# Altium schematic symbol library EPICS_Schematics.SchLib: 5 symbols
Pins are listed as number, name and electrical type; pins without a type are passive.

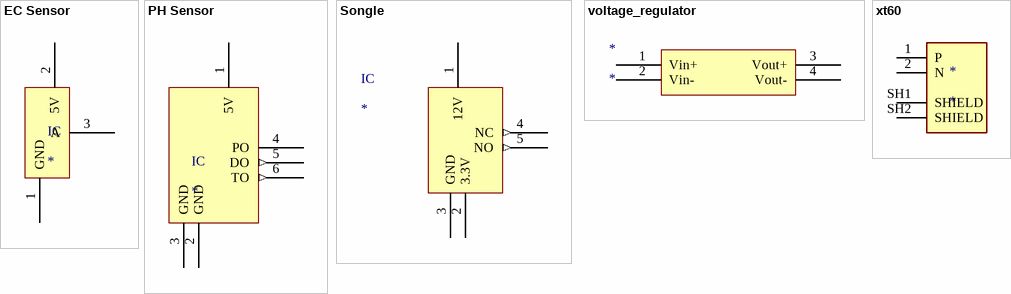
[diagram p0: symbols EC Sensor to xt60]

## EC Sensor
designator IC
pins: 1 GND (power), 2 5V (power), 3 A

## PH Sensor
designator IC
pins: 1 5V (power), 2 GND (power), 3 GND (power), 4 PO, 5 DO (out), 6 TO (out)

## Songle
designator IC
pins: 1 12V (power), 2 3.3V (power), 3 GND (power), 4 NC (out), 5 NO (out)

## voltage_regulator
designator *
pins: 1 Vin+, 2 Vin-, 3 Vout+, 4 Vout-

## xt60
designator *
pins: 1 P, 2 N, SH1 SHIELD, SH2 SHIELD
